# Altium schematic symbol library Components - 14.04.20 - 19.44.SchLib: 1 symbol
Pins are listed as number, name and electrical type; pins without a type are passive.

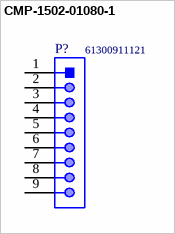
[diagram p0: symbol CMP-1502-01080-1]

## CMP-1502-01080-1
designator P?, comment 61300911121
THT Vertical Pin Header WR-PHD, Pitch 2.54 mm, Single Row, 9 pins; Manufacturer: Wurth Elektronik; Pitch: 2.54mm; Gender: Male; Working Voltage: 250VAC; Contact Resistance: 20mOhm; Withstanding Voltage: 500VAC; Pin Number: 9; Rated Current: 3A
footprint 61300911121 (Pin Header, pitch 2.54 mm, THT, Vertical, single row, 9p)
pins: 1, 2, 3, 4, 5, 6, 7, 8, 9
